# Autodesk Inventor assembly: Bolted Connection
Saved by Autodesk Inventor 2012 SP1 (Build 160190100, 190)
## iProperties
Created: 2006-09
Part Number: Bolted Connection
Document SubType Name: Assembly
ClientObjectVersion: 1
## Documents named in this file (3)
- D:\Backup\CMU Work Temp\XX\Inv2012DynSim\Sub-Assemblies\Bolted Connection6.iam
- D:\Backup\CMU Work Temp\XX\Inv2012DynSim\Parts\M5-16.ipt
- D:\Backup\CMU Work Temp\XX\Inv2012DynSim\Parts\M5.ipt
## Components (2 placed, 2 different names)
1. Indented Hex Head Machine Screw - Metric M5 x 0.8 x 16:1
2. DIN 6923 M5:1
